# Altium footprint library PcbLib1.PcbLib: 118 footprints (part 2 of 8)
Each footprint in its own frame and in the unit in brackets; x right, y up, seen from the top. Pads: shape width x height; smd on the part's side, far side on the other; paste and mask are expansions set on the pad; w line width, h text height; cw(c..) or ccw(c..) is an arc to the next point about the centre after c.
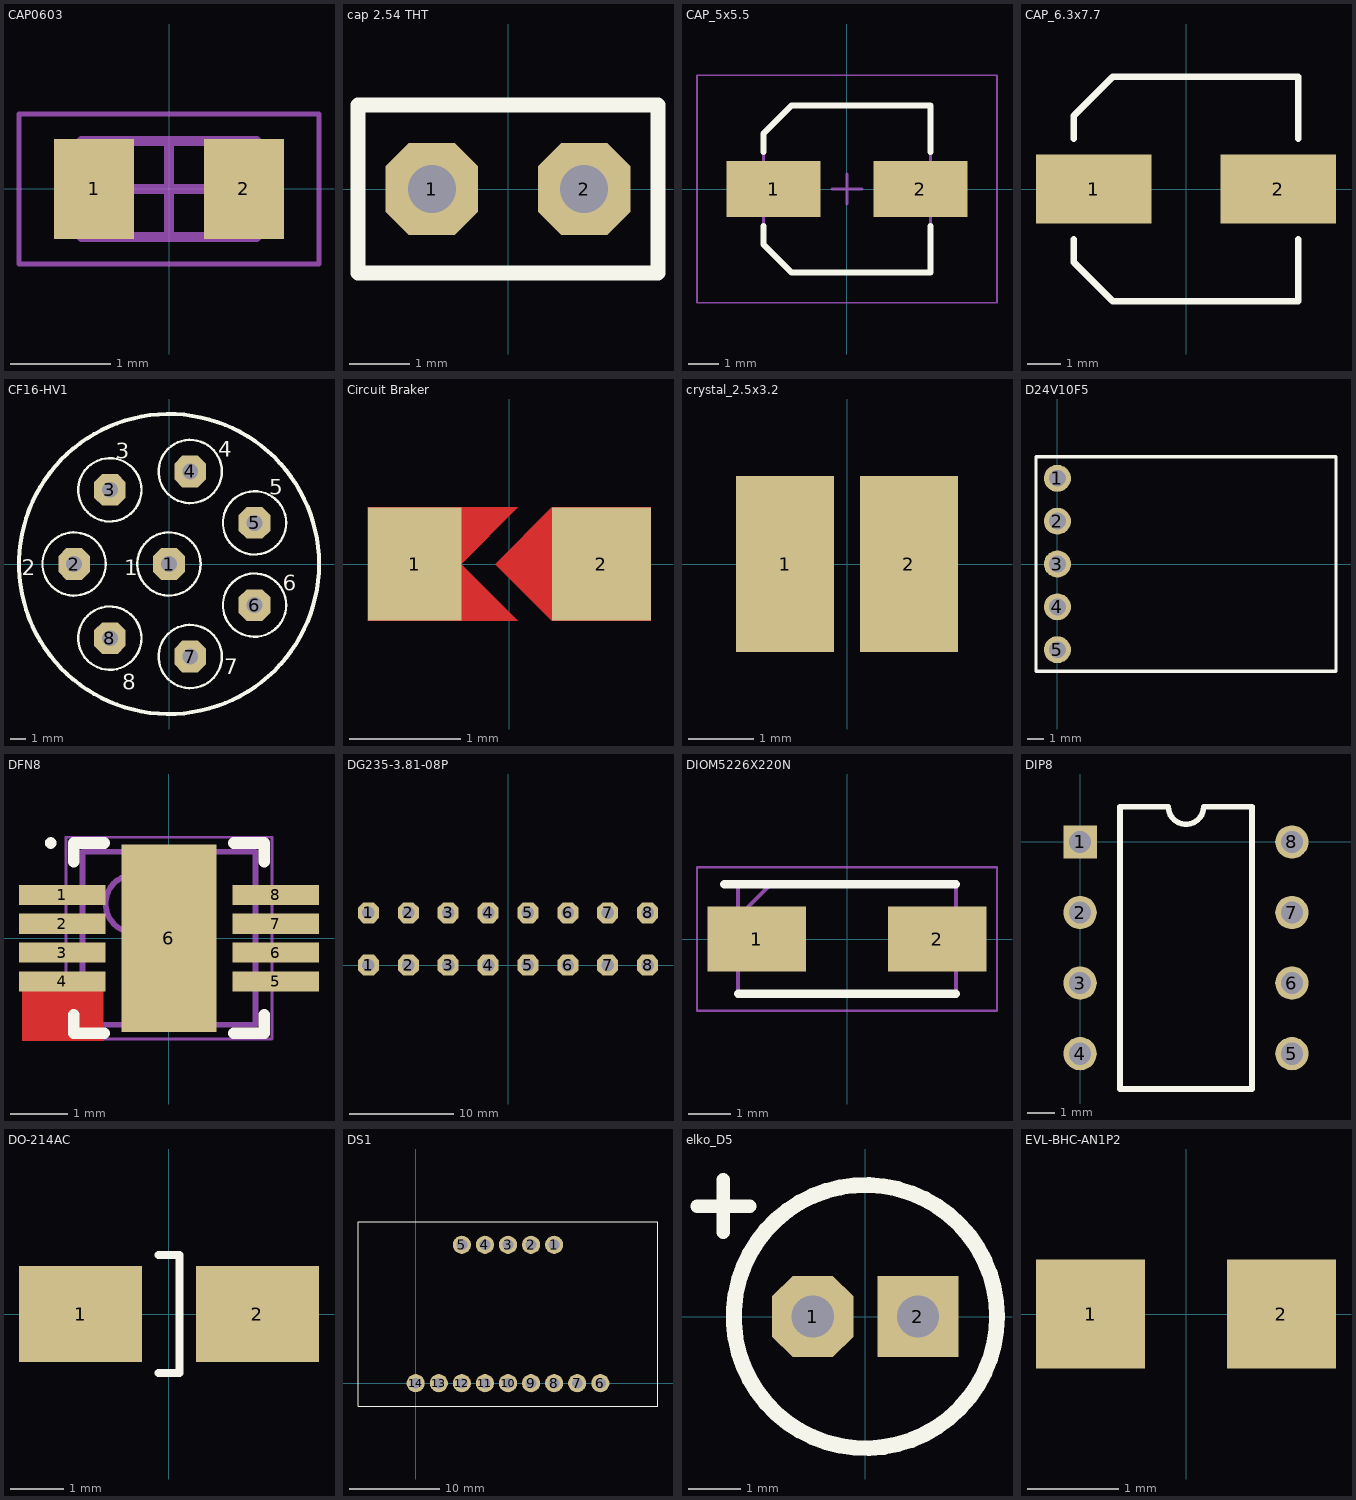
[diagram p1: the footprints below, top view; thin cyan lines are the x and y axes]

## CAP0603 [mm]
height 0.87
pads (2):
  rect 0.8x1 smd mask+0.035: 1(-0.75,0) 2(0.75,0)
Mechanical 13:
  lines w0.1: -0.875,-0.48 0.875,-0.48 0.875,0.48 -0.875,0.48 -0.875,-0.48
Mechanical 15:
  lines w0.05: -1.5,-0.75 1.5,-0.75 1.5,0.75 -1.5,0.75 -1.5,-0.75
  lines w0.1: -0.48,0 0.48,0 ; 0,-0.48 0,0.48
3D body "CAP0603.step": height 0.87, standoff 0, extent -0.875,-0.48 0.875,0.48

## cap 2.54 THT [mm] "ceramic THT capacitor"
pads (2):
  oct 1.54x1.54 hole 0.8: 1(-1.27,0) 2(1.27,0)
Top Overlay:
  lines w0.254: -2.5,-1.4 -2.5,1.4 2.5,1.4 2.5,-1.4 -2.5,-1.4
3D body "cap_254.step": height 5.16, standoff -6.5, extent -1.905,-1.3 1.905,1.245

## CAP_5x5.5 [mm] "Aluminum Electrolytic Capacitor, Body 5,30x5,30x5,80mm, IPC Low Density"
height 5.8
pads (2):
  rect 3.1x1.85 smd: 1(-2.425,0) 2(2.425,0)
Top Overlay:
  lines w0.2: -2.75,-1.225 -2.75,-1.837 -1.837,-2.75 2.75,-2.75 2.75,-1.225 ; -2.75,1.225 -2.75,1.837 -1.837,2.75 2.75,2.75 2.75,1.225
Mechanical 13:
  lines w0.1: -2.75,-1.837 -1.837,-2.75 2.75,-2.75 2.75,2.75 -1.837,2.75 -2.75,1.837 -2.75,-1.837
Mechanical 15:
  lines w0.05: -4.95,-3.75 -4.95,3.75 4.95,3.75 4.95,-3.75 -4.95,-3.75
  lines w0.1: -0.5,0 0.5,0 ; 0,-0.5 0,0.5
3D body "CAPAE6353X58M.step": height 5.8, standoff 0, extent -3.15,-2.75 3.15,2.75

## CAP_6.3x7.7 [mm] "6,3x7,7"
height 7.7
pads (2):
  rect 3.5x2.1 smd: 1(-2.8,0) 2(2.8,0)
Top Overlay:
  lines w0.2: -3.4,-1.524 -3.4,-2.225 -2.225,-3.4 3.4,-3.4 3.4,-1.524 ; -3.4,1.524 -3.4,2.225 -2.225,3.4 3.4,3.4 3.4,1.524
3D body "CAP_.step": height 7.7, standoff 0, extent -3.4,-3.4 3.4,3.4

## CF16-HV1 [mm]
pads (8):
  oct 2x2 hole 1 mask+0.05: 1(0,0) 2(-6,0) 3(-3.74,4.69) 4(1.34,5.85) 5(5.41,2.6) 6(5.41,-2.6) 7(1.34,-5.85) 8(-3.74,-4.69)
Top Overlay:
  circle w0.254: c0,0 r9.485
  circle w0.15: c-3.74,4.69 r2
  circle w0.15: c1.34,5.85 r2
  circle w0.15: c5.41,2.6 r2
  circle w0.15: c5.41,-2.6 r2
  circle w0.15: c1.34,-5.85 r2
  circle w0.15: c-3.74,-4.69 r2
  circle w0.15: c-6,0 r2
  circle w0.15: c0,0 r2
  text "1" at -2.845,-0.7 h1
  text "2" at -9.3,-0.7 h1
  text "3" at -3.353,6.655 h1
  text "4" at 3.099,6.782 h1
  text "5" at 6.35,4.394 h1
  text "6" at 7.188,-1.702 h1
  text "7" at 3.505,-6.985 h1
  text "8" at -2.946,-7.95 h1

## Circuit Braker [mil] "Circuit Braker"
pads (2):
  rect 33x40 smd mask+0: 1(-33.5,0)
  rect 35x40 smd mask+0: 2(32.5,0)
Top Layer:
  region: 50,20
  region: 15,20 50,20 50,-20 15,-20 -5,0
  region: -50,20 -50,-20 3,-20 -17,0 3,20
Top Solder:
  region: -52,-22 8,-22 -14,0 8,22 -52,22
  region: -8,0 14,-22 52,-22 52,22 14,22

## crystal_2.5x3.2 [mm]
pads (2):
  rect 1.5x2.7 smd: 1(-0.95,0) 2(0.95,0)
3D body "NX3225GD.step": height 1.1, standoff 0, extent -1.6,-1.25 1.6,1.25

## D24V10F5 [mm]
pads (5):
  round 1.6 hole 1: 1(0,5.08) 2(0,2.54) 3(0,0) 4(0,-2.54) 5(0,-5.08)
Top Overlay:
  lines w0.2: -1.27,-6.35 16.51,-6.35 16.51,6.35 -1.27,6.35 -1.27,-6.35
3D body "d24v10fx.STEP": height 6.36, standoff -2.99, extent -1.27,-6.35 16.51,6.35

## DFN8 [mm] "DFN, 8-Leads, Body 3,00x3,00mm, Pitch 0,50mm"
height 1
pads (9):
  rect 1.5x0.35 smd: 1(-1.85,0.75) 2(-1.85,0.25) 3(-1.85,-0.25) 4(-1.85,-0.75) 5(1.85,-0.75) 6(1.85,-0.25) 7(1.85,0.25) 8(1.85,0.75)
  rect 1.64x3.25 smd: 6(0,0)
Top Layer:
  region: -2.54,-0.889 -2.54,-1.778 -1.143,-1.778 -1.143,-0.889
Top Overlay:
  circle w0.1: c-2.05,1.65 r0.05
  lines w0.2: -1.65,-1.325 -1.65,-1.65 -1.12,-1.65 ; -1.65,1.325 -1.65,1.65 -1.12,1.65 ; 1.12,-1.65 1.65,-1.65 1.65,-1.325 ; 1.12,1.65 1.65,1.65 1.65,1.325
Mechanical 13:
  circle w0.1: c-0.6,0.6 r0.5
  lines w0.1: -1.5,-1.5 -1.5,1.5 1.5,1.5 1.5,-1.5 -1.5,-1.5
Mechanical 15:
  lines w0.05: -1.785,-1.75 -1.785,1.75 1.785,1.75 1.785,-1.75 -1.785,-1.75
  lines w0.1: -0.5,0 0.5,0 ; 0,-0.5 0,0.5
3D body "DFN8.step": height 1, standoff 0, extent -1.501,-1.5 1.501,1.5

## DG235-3.81-08P [mm]
pads (16):
  oct 2x2 hole 1.2 mask+0.05: 1(-13.335,0) 1(-13.335,5) 2(-9.525,0) 2(-9.525,5) 3(-5.715,0) 3(-5.715,5) 4(-1.905,0) 4(-1.905,5) 5(1.905,0) 5(1.905,5) 6(5.715,0) 6(5.715,5) 7(9.525,0) 7(9.525,5) 8(13.335,0) 8(13.335,5)
3D body "DG235-3.81-08P-1Y-00A(H).stp": height 15.5, standoff -3.6, extent -16.002,-4.472 16.078,8.028

## DIOM5226X220N [mm]
pads (2):
  rect 2.35x1.55 smd: 1(-2.15,0) 2(2.15,0)
Top Overlay:
  lines w0.2: -2.925,1.302 2.598,1.302 ; -2.598,-1.302 2.598,-1.302
Mechanical 15:
  lines w0.1: -2.598,0.528 -1.822,1.302 ; -2.598,-1.302 2.598,-1.302 2.598,1.302 -2.598,1.302 -2.598,-1.302
Mechanical 20:
  lines w0.05: -3.575,-1.71 3.575,-1.71 3.575,1.71 -3.575,1.71 -3.575,-1.71

## DIP8 [mm]
pads (8):
  rect 1.2x1.2 hole 0.8: 1(0,0)
  round 1.2 hole 0.8: 2(0,-2.54) 3(0,-5.08) 4(0,-7.62) 5(7.62,-7.62) 6(7.62,-5.08) 7(7.62,-2.54) 8(7.62,0)
Top Overlay:
  lines w0.2: 1.435,-8.89 1.435,1.27 3.175,1.27 ccw(c3.81,1.27) 4.445,1.27 6.185,1.27 6.185,-8.89 1.435,-8.89

## DO-214AC [mm] "Molded Diode, 2-Leads, Body 4,31x2,49mm"
height 2.31
pads (2):
  rect 2.3x1.8 smd: 1(-1.65,0) 2(1.65,0)
Top Overlay:
  lines w0.15: -0.2,-1.1 0.2,-1.1 0.2,1.1 -0.2,1.1
3D body "DO-214AC.step": height 2.31, standoff 0, extent -2.505,-1.09 2.505,1.09

## DS1 [mm]
pads (14):
  round 2 hole 1.2 mask+0.05: 1(15.24,15.24) 2(12.7,15.24) 3(10.16,15.24) 4(7.62,15.24) 5(5.08,15.24) 6(20.32,0) 7(17.78,0) 8(15.24,0) 9(12.7,0) 10(10.16,0) 11(7.62,0) 12(5.08,0) 13(2.54,0) 14(0,0)
Top Overlay:
  lines w0.1: 26.67,-2.54 26.67,17.78 -6.35,17.78 -6.35,-2.54 26.67,-2.54 ; 26.67,-2.54 26.67,-2.54

## elko_D5 [mm] "5mm diameter THT elko"
pads (2):
  oct 1.54x1.54 hole 0.8: 1(-1,0)
  rect 1.54x1.54 hole 0.8: 2(1,0)
Top Overlay:
  circle w0.3: c0,0 r2.502
  lines w0.254: -3.2,2.1 -2.2,2.1 ; -2.7,1.6 -2.7,2.6
3D body "elko_2x5.5x12.step": height 12, standoff -1.78, extent -2.751,-2.751 2.75,2.751

## EVL-BHC-AN1P2 [mm] "0805_Blue"
pads (2):
  rect 1.2x1.2 smd: 1(-1.05,0) 2(1.05,0)
3D body "EVL-BHC-AN1P2.STEP": height 1.1, standoff 0, extent -1,-0.625 1,0.625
